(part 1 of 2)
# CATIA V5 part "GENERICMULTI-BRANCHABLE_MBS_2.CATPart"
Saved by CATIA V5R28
Part number: GENERICMULTI-BRANCHABLE_MBS_2
Revision: ---
Publications: "SegmentExtremity.1", "SegmentExtremity.2", "ElecLogTerm.1", "Flexible Curve.1", "Point.4", "SegmentExtremity.3", "SegmentExtremity.4", "ElecLogTerm.2", "Flexible Curve.2", "Point.6", "Point.9", "SegmentExtremity.5", "SegmentExtremity.6", "ElecLogTerm.3", "Flexible Curve.3", "Point.20", "SegmentExtremity.7", "SegmentExtremity.8", "ElecLogTerm.4", "Flexible Curve.4", "CPoint.24", "SegmentExtremity.9", "SegmentExtremity.10", "ElecLogTerm.5", "Flexible Curve.5", "SegmentExtremity.11", "SegmentExtremity.12", "ElecLogTerm.6", "Flexible Curve.6", "SegmentExtremity.13", "SegmentExtremity.14", "ElecLogTerm.7", "Flexible Curve.7", "SegmentExtremity.15", "SegmentExtremity.16", "ElecLogTerm.8", "Flexible Curve.8", "Point.43", "Point.48", "SegmentExtremity.17", "SegmentExtremity.18", "ElecLogTerm.9", "Flexible Curve.9", "SegmentExtremity.19", "SegmentExtremity.20", "ElecLogTerm.10", "Flexible Curve.10", "SegmentExtremity.21", "SegmentExtremity.22", "ElecLogTerm.11", "Flexible Curve.11", "SegmentExtremity.23", "SegmentExtremity.24", "ElecLogTerm.12", "Flexible Curve.12", "SegmentExtremity.25", "SegmentExtremity.26", "ElecLogTerm.13", "Flexible Curve.13", "SegmentExtremity.27", "SegmentExtremity.28", "ElecLogTerm.14", "Flexible Curve.14", "SegmentExtremity.29", "SegmentExtremity.30", "ElecLogTerm.15", "Flexible Curve.15", "SegmentExtremity.31", "SegmentExtremity.32", "ElecLogTerm.16", "Flexible Curve.16", "Point.74", "SegmentExtremity.33", "SegmentExtremity.34", "ElecLogTerm.17", "Flexible Curve.17", "Point.77", "SegmentExtremity.35", "SegmentExtremity.36", "ElecLogTerm.18", "Flexible Curve.18", "SegmentExtremity.37", "SegmentExtremity.38", "ElecLogTerm.19", "Flexible Curve.19", "SegmentExtremity.39", "SegmentExtremity.40", "ElecLogTerm.20", "Flexible Curve.20", "Point.85", "Point.86", "SegmentExtremity.41", "SegmentExtremity.42", "ElecLogTerm.21", "Flexible Curve.21", "SegmentExtremity.43", "SegmentExtremity.44", "ElecLogTerm.22", "Flexible Curve.22", "SegmentExtremity.45", "SegmentExtremity.46", "ElecLogTerm.23", "Flexible Curve.23", "Point.94", "Point.96", "SegmentExtremity.47", "SegmentExtremity.48", "ElecLogTerm.24", "Flexible Curve.24", "SegmentExtremity.49", "SegmentExtremity.50", "ElecLogTerm.25", "Flexible Curve.25", "SegmentExtremity.51", "SegmentExtremity.52", "ElecLogTerm.26", "Flexible Curve.26", "Point.105", "Point.110", "SegmentExtremity.53", "SegmentExtremity.54", "ElecLogTerm.27", "Flexible Curve.27", "Point.117", "SegmentExtremity.55", "SegmentExtremity.56", "ElecLogTerm.28", "Flexible Curve.28", "SegmentExtremity.57", "SegmentExtremity.58", "ElecLogTerm.29", "Flexible Curve.29", "Point.189", "SegmentExtremity.59", "SegmentExtremity.60", "ElecLogTerm.30", "Flexible Curve.30", "Point.229", "SegmentExtremity.61", "SegmentExtremity.62", "ElecLogTerm.31", "Flexible Curve.31", "Point.236", "SegmentExtremity.63", "SegmentExtremity.64", "ElecLogTerm.32", "Flexible Curve.32", "Point.239", "SegmentExtremity.65", "SegmentExtremity.66", "ElecLogTerm.33", "Flexible Curve.33", "SegmentExtremity.67", "SegmentExtremity.68", "ElecLogTerm.34", "Flexible Curve.34", "Point.301", "SegmentExtremity.69", "SegmentExtremity.70", "ElecLogTerm.35", "Flexible Curve.35", "Point.339", "SegmentExtremity.71", "SegmentExtremity.72", "ElecLogTerm.36", "Flexible Curve.36", "Point.371", "SegmentExtremity.73", "SegmentExtremity.74", "ElecLogTerm.37", "Flexible Curve.37", "Point.377", "SegmentExtremity.75", "SegmentExtremity.76", "ElecLogTerm.38", "Flexible Curve.38", "SegmentExtremity.77", "SegmentExtremity.78", "ElecLogTerm.39", "Flexible Curve.39", "Point.394", "SegmentExtremity.79", "SegmentExtremity.80", "ElecLogTerm.40", "Flexible Curve.40", "Point.399", "SegmentExtremity.81", "SegmentExtremity.82", "ElecLogTerm.41", "Flexible Curve.41", "SegmentExtremity.83", "SegmentExtremity.84", "ElecLogTerm.42", "Flexible Curve.42", "SegmentExtremity.85", "SegmentExtremity.86", "ElecLogTerm.43", "Flexible Curve.43", "Point.407", "SegmentExtremity.87", "SegmentExtremity.88", "ElecLogTerm.44", "Flexible Curve.44", "Point.412", "Point.413", "SegmentExtremity.89", "SegmentExtremity.90", "ElecLogTerm.45", "Flexible Curve.45", "SegmentExtremity.91", "SegmentExtremity.92", "ElecLogTerm.46", "Flexible Curve.46", "SegmentExtremity.93", "SegmentExtremity.94", "ElecLogTerm.47", "Flexible Curve.47", "SegmentExtremity.95", "SegmentExtremity.96", "ElecLogTerm.48", "Flexible Curve.48", "Point.428", "SegmentExtremity.97", "SegmentExtremity.98", "ElecLogTerm.49", "Flexible Curve.49", "SegmentExtremity.99", "SegmentExtremity.100", "ElecLogTerm.50", "Flexible Curve.50", "SegmentExtremity.101", "SegmentExtremity.102", "ElecLogTerm.51", "Flexible Curve.51", "SegmentExtremity.103", "SegmentExtremity.104", "ElecLogTerm.52", "Flexible Curve.52", "Point.475", "SegmentExtremity.105", "SegmentExtremity.106", "ElecLogTerm.53", "Flexible Curve.53", "Point.494", "SegmentExtremity.107", "SegmentExtremity.108", "ElecLogTerm.54", "Flexible Curve.54", "BCPRPoint.2", "BCPRPoint.3", "BCPRPoint.4", "BCPRPoint.5", "BCPRPoint.6", "BCPRPoint.7", "BCPRPoint.8", "BCPRPoint.9", "BCPRPoint.10", "BCPRPoint.11", "BCPRPoint.12", "BCPRPoint.13", "BCPRPoint.14", "BCPRPoint.15", "BCPRPoint.16", "BCPRPoint.17", "BCPRPoint.18", "BCPRPoint.19", "BCPRPoint.20", "BCPRPoint.21", "BCPRPoint.22", "Point.525", "Point.526", "Point.527", "Point.528", "Point.529", "Point.530", "Point.531", "Point.532", "Point.533", "Point.534", "Point.537", "Point.538", "Point.539", "Point.540", "Point.541", "Point.542", "Point.543", "Point.544", "Point.545", "Point.546", "Point.547", "Point.548", "Point.549", "Point.550", "Point.551", "Point.552", "Point.554", "Point.555", "Point.556", "Point.557", "Point.558", "Point.559", "Point.560", "Point.561", "Point.562", "Point.563", "Point.564", "Point.565", "Point.566", "Point.567", "Point.568", "Point.569", "Point.570", "Point.571", "Point.572", "Point.573", "Point.574", "Point.179", "BCPRPoint.23", "Point.670", "Point.667", "Point.668", "Point.669", "Point.683", "Project.2", "Point.710", "SegmentExtremity.109", "SegmentExtremity.110", "ElecLogTerm.55", "Flexible Curve.55", "BCPRPoint_generated(BCP).1", "SegmentExtremity.111", "SegmentExtremity.112", "ElecLogTerm.56", "Flexible Curve.56", "BCPRPoint_generated(BCP).2", "BCPRPoint_generated(BCP).3", "SegmentExtremity.113", "SegmentExtremity.114", "ElecLogTerm.57", "Point.729", "SegmentExtremity.115", "SegmentExtremity.116", "ElecLogTerm.58", "Flexible Curve.57", "BCPRPoint_generated(BCP).4", "SegmentExtremity.117", "SegmentExtremity.118", "ElecLogTerm.59", "Flexible Curve.58", "BCPRPoint_generated(BCP).5", "BCPRPoint_generated(BCP).6", "BCPRPoint_generated(BCP).7", "SegmentExtremity.119", "SegmentExtremity.120", "ElecLogTerm.60", "Flexible Curve.59", "BCPRPoint_generated(BCP).8", "Point.408", "Point.409", "Point.467", "Point.466"
Bounding box of the stored display mesh (mm): x 24243.072 to 33945.086, y -22409.492 to -1507.375, z 3643.49 to 6313.591
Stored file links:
  C:\Users\ajc8720\Documents\BOEING_WORK\0001-2CES\004-AP242\Boeing-Generic_Harness_R3\GENERICMULTI-BRANCHABLE_MBS_2.CATPart
  C:\Users\ajc8720\Documents\BOEING_WORK\0001-2CES\004-AP242\Boeing-Generic_Harness_R3\GENERICBUNDLE_GBN_1.CATProduct
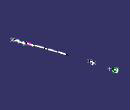
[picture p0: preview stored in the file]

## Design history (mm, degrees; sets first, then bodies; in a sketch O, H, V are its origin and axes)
Sketch1 on {plane type Normal, RefPoint {point type OnCurve, Real 0.5}}, origin (26213.183, -6443.2858, 4604.0933), H (0.9576, 0.2864, -0.0301), V (0, 0.1045, 0.9945)
  circle A1 centre (0, 0) radius 10.795
  point P1 (0, 0)
  reference projected point E1 (0, 0) from {point type OnCurve, Real 0.5}
  radius A1 = 10.795
  distance E1 P1 = 0
ElecRouteBody1
EhiBundleSegmentBody1
Sketch2 on {plane type Normal, RefPoint {point type OnCurve, Real 0.5}}, origin (26256.4001, -6641.2399, 4721.1042), H (0.9062, 0.4205, -0.0442), V (0, 0.1045, 0.9945)
  circle A1 centre (0, 0) radius 9.525
  point P1 (0, 0)
  reference projected point E1 (0, 0) from {point type OnCurve, Real 0.5}
  radius A1 = 9.525
  distance E1 P1 = 0
ElecRouteBody2
EhiBundleSegmentBody2
Sketch3 on {plane type Normal, RefPoint {point type OnCurve, Real 0.5}}, origin (26453.1949, -6991.596, 4803.1154), H (0.93, 0.3504, -0.111), V (0.0006, 0.3004, 0.9538)
  circle A1 centre (-0.9208, 0.0537) radius 9.525
  point P1 (-0.9208, 0.0537)
  reference projected point E1 (-0.9208, 0.0537) from {point type OnCurve, Real 0.5}
  radius A1 = 9.525
  distance E1 P1 = 0
ElecRouteBody3
EhiBundleSegmentBody3
Sketch4 on {plane type Normal, RefPoint {point type OnCurve, Real 0.5}}, origin (26668.956, -7391.5002, 4859.3676), H (0.8885, 0.4564, -0.047), V (0, 0.1023, 0.9947)
  circle A1 centre (0, 0) radius 9.525
  point P1 (0, 0)
  reference projected point E1 (0, 0) from {point type OnCurve, Real 0.5}
  radius A1 = 9.525
  distance E1 P1 = 0
ElecRouteBody4
EhiBundleSegmentBody4
Sketch5 on {plane type Normal, RefPoint {point type OnCurve, Real 0.5}}, origin (27011.036, -6318.2009, 4593.2911), H (0.1287, -0.1353, 0.9824), V (0.0331, 0.9907, 0.1321)
  circle A1 centre (-20.9065, -19.5121) radius 4.0551
  point P1 (-20.9065, -19.5121)
  reference projected point E1 (-20.9065, -19.5121) from {point type OnCurve, Real 0.5}
  radius A1 = 4.0551
  distance E1 P1 = 0
ElecRouteBody5
EhiBundleSegmentBody5
Sketch6 on {plane type Normal, RefPoint {point type OnCurve, Real 0.5}}, origin (49731.4801, -39351.1877, 111363.943), H (-0.0398, 0.9992, 0.0075), V (-0.1997, -0.0006, -0.9799)
  circle A1 centre (32927.0187, 109125.9194) radius 4.0551
  point P1 (32927.0187, 109125.9194)
  reference projected point E1 (32927.0187, 109125.9194) from {point type OnCurve, Real 0.5}
  radius A1 = 4.0551
  distance E1 P1 = 0
ElecRouteBody6
EhiBundleSegmentBody6
Sketch7 on {plane type Normal, RefPoint {point type OnCurve, Real 0.5}}, origin (26989.497, -6324.5713, 4603.6628), H (0.3995, -0.7235, 0.5629), V (-0.0699, 0.5882, 0.8057)
  circle A1 centre (-12.6154, -10.6018) radius 1.905
  point P1 (-12.6154, -10.6018)
  reference projected point E1 (-12.6154, -10.6018) from {point type OnCurve, Real 0.5}
  radius A1 = 1.905
  distance E1 P1 = 0
ElecRouteBody7
EhiBundleSegmentBody7
Sketch8 on {plane type Normal, RefPoint {point type OnCurve, Real 0.5}}, origin (26896.1491, -7390.6456, 4843.5268), H (0.1109, -0.1106, 0.9877), V (0, 0.9938, 0.1112)
  circle A1 centre (0, 0) radius 4.1275
  point P1 (0, 0)
  reference projected point E1 (0, 0) from {point type OnCurve, Real 0.5}
  radius A1 = 4.1275
  distance E1 P1 = 0
ElecRouteBody8
EhiBundleSegmentBody8
Sketch9 on {plane type Normal, RefPoint {point type OnCurve, Real 0.5}}, origin (26695.6549, -7366.8722, 4853.3831), H (0.3387, 0.9392, 0.0562), V (-0.0089, 0.0629, -0.998)
  circle A1 centre (-5.2532, -1.0249) radius 4.1275
  point P1 (-5.2532, -1.0249)
  reference projected point E1 (-5.2532, -1.0249) from {point type OnCurve, Real 0.5}
  radius A1 = 4.1275
  distance E1 P1 = 0
ElecRouteBody9
EhiBundleSegmentBody9
Sketch10 on {plane type Normal, RefPoint {point type OnCurve, Real 0.5}}, origin (26236.2396, -6563.4435, 4663.301), H (0.9909, 0.0973, -0.0929), V (0, -0.6903, -0.7235)
  circle A1 centre (0, 0) radius 6.35
  point P1 (0, 0)
  reference projected point E1 (0, 0) from {point type OnCurve, Real 0.5}
  radius A1 = 6.35
  distance E1 P1 = 0
ElecRouteBody10
EhiBundleSegmentBody10
Sketch11 on {plane type Normal, RefPoint {point type OnCurve, Real 0.5}}, origin (27049.1119, -7384.3587, 4761.522), H (0.9245, -0.0602, -0.3763), V (0, 0.9874, -0.158)
  circle A1 centre (0, 0) radius 2.54
  point P1 (0, 0)
  reference projected point E1 (0, 0) from {point type OnCurve, Real 0.5}
  radius A1 = 2.54
  distance E1 P1 = 0
ElecRouteBody11
EhiBundleSegmentBody11
Sketch12 on {plane type Normal, RefPoint {point type OnCurve, Real 0.5}}, origin (26128.5708, -5138.6732, 4494.0283), H (0.4828, 0.1657, -0.8599), V (0.1158, -0.9854, -0.1249)
  circle A1 centre (-1.9758, -6.4321) radius 1.905
  point P1 (-1.9758, -6.4321)
  reference projected point E1 (-1.9758, -6.4321) from {point type OnCurve, Real 0.5}
  radius A1 = 1.905
  distance E1 P1 = 0
ElecRouteBody12
EhiBundleSegmentBody12
Sketch13 on {plane type Normal, RefPoint {point type OnCurve, Real 0.5}}, origin (26107.9693, -5243.6064, 4514.0548), H (0.4828, 0.1659, -0.8599), V (0.1159, -0.9854, -0.125)
  circle A1 centre (-1.9849, -6.4169) radius 1.905
  point P1 (-1.9849, -6.4169)
  reference projected point E1 (-1.9849, -6.4169) from {point type OnCurve, Real 0.5}
  radius A1 = 1.905
  distance E1 P1 = 0
ElecRouteBody13
EhiBundleSegmentBody13
Sketch14 on {plane type Normal, RefPoint {point type OnCurve, Real 0.5}}, origin (26097.0495, -5135.4084, 4453.8298), H (0.9908, -0.1276, -0.0444), V (-0.0273, 0.1326, -0.9908)
  circle A1 centre (-20.4324, 12.3549) radius 3.81
  point P1 (-20.4324, 12.3549)
  reference projected point E1 (-20.4324, 12.3549) from {point type OnCurve, Real 0.5}
  radius A1 = 3.81
  distance E1 P1 = 0
ElecRouteBody14
EhiBundleSegmentBody14
Sketch15 on {plane type Normal, RefPoint {point type OnCurve, Real 0.5}}, origin (26102.9361, -5259.1919, 4430.3629), H (0.9027, 0.2796, 0.3272), V (-0.0137, 0.7785, -0.6274)
  circle A1 centre (-3.249, 5.8767) radius 3.81
  point P1 (-3.249, 5.8767)
  reference projected point E1 (-3.249, 5.8767) from {point type OnCurve, Real 0.5}
  radius A1 = 3.81
  distance E1 P1 = 0
ElecRouteBody15
EhiBundleSegmentBody15
Sketch16 on {plane type Normal, RefPoint {point type OnCurve, Real 0.5}}, origin (26042.6946, -5529.0738, 4602.6872), H (0.4364, -0.7464, 0.5025), V (0.0348, 0.572, 0.8195)
  circle A1 centre (9.9402, -2.3183) radius 2.54
  point P1 (9.9402, -2.3183)
  reference projected point E1 (9.9402, -2.3183) from {point type OnCurve, Real 0.5}
  radius A1 = 2.54
  distance E1 P1 = 0
ElecRouteBody16
EhiBundleSegmentBody16
Sketch17 on {plane type Normal, RefPoint {point type OnCurve, Real 0.5}}, origin (25968.1593, -5541.3146, 4616.3826), H (0.0351, -0.0718, -0.9968), V (0, -0.9974, 0.0719)
  circle A1 centre (0, 0) radius 2.54
  point P1 (0, 0)
  reference projected point E1 (0, 0) from {point type OnCurve, Real 0.5}
  radius A1 = 2.54
  distance E1 P1 = 0
ElecRouteBody17
EhiBundleSegmentBody17
Sketch18 on {plane type Normal, RefPoint {point type OnCurve, Real 0.5}}, origin (25928.9352, -5542.4868, 4617.775), H (0.1622, -0.1298, 0.9782), V (-0.0107, 0.991, 0.1333)
  circle A1 centre (-1.6298, -0.282) radius 1.905
  point P1 (-1.6298, -0.282)
  reference projected point E1 (-1.6298, -0.282) from {point type OnCurve, Real 0.5}
  radius A1 = 1.905
  distance E1 P1 = 0
ElecRouteBody18
EhiBundleSegmentBody18
Sketch19 on {plane type Normal, RefPoint {point type OnCurve, Real 0.5}}, origin (25969.5148, -5543.6441, 4618.1771), H (0.51, -0.5087, 0.6936), V (0, -0.8064, -0.5914)
  circle A1 centre (0, 0) radius 1.905
  point P1 (0, 0)
  reference projected point E1 (0, 0) from {point type OnCurve, Real 0.5}
  radius A1 = 1.905
  distance E1 P1 = 0
ElecRouteBody19
EhiBundleSegmentBody19
Sketch20 on {plane type Normal, RefPoint {point type OnCurve, Real 0.5}}, origin (30670.7863, -16023.3411, 5695.8425), H (0.0495, 0.3386, -0.9396), V (0.0176, 0.9403, 0.3398)
  circle A1 centre (-1.9655, -2.0978) radius 4.4577
  point P1 (-1.9655, -2.0978)
  reference projected point E1 (-1.9655, -2.0978) from {point type OnCurve, Real 0.5}
  radius A1 = 4.4577
  distance E1 P1 = 0
ElecRouteBody20
EhiBundleSegmentBody20
Sketch21 on {plane type Normal, RefPoint {point type OnCurve, Real 0.5}}, origin (30705.4895, -15985.8971, 5696.0522), H (0.9904, 0.1378, -0.0101), V (0, -0.0734, -0.9973)
  circle A1 centre (0, 0) radius 4.4577
  point P1 (0, 0)
  reference projected point E1 (0, 0) from {point type OnCurve, Real 0.5}
  radius A1 = 4.4577
  distance E1 P1 = 0
ElecRouteBody21
EhiBundleSegmentBody21
Sketch22 on {plane type Normal, RefPoint {point type OnCurve, Real 0.5}}, origin (30698.767, -15966.8699, 5655.2829), H (0.999, -0.045, 0.0086), V (0, 0.1871, 0.9823)
  circle A1 centre (0, 0) radius 1.905
  point P1 (0, 0)
  reference projected point E1 (0, 0) from {point type OnCurve, Real 0.5}
  radius A1 = 1.905
  distance E1 P1 = 0
ElecRouteBody22
EhiBundleSegmentBody22
Sketch23 on {plane type Normal, RefPoint {point type OnCurve, Real 0.5}}, origin (28685.6847, -11813.3322, 5280.2662), H (0.8036, -0.0518, 0.5929), V (-0.0111, 0.9947, 0.102)
  circle A1 centre (-0.5557, -3.6236) radius 3.81
  point P1 (-0.5557, -3.6236)
  reference projected point E1 (-0.5557, -3.6236) from {point type OnCurve, Real 0.5}
  radius A1 = 3.81
  distance E1 P1 = 0
ElecRouteBody23
EhiBundleSegmentBody23
Sketch24 on {plane type Normal, RefPoint {point type OnCurve, Real 0.5}}, origin (28677.0755, -11774.8153, 5303.0023), H (0.798, -0.5947, 0.0978), V (0, -0.1622, -0.9868)
  circle A1 centre (0.0001, 0) radius 3.81
  point P1 (0.0001, 0)
  reference projected point E1 (0.0001, 0) from {point type OnCurve, Real 0.5}
  radius A1 = 3.81
  distance E1 P1 = 0
ElecRouteBody24
EhiBundleSegmentBody24
Sketch25 on {plane type Normal, RefPoint {point type OnCurve, Real 0.5}}, origin (28722.2891, -11781.9897, 5268.5204), H (0.8943, -0.4309, 0.1207), V (-0.0577, -0.3785, -0.9238)
  circle A1 centre (3.5246, 5.3989) radius 1.905
  point P1 (3.5246, 5.3989)
  reference projected point E1 (3.5246, 5.3989) from {point type OnCurve, Real 0.5}
  radius A1 = 1.905
  distance E1 P1 = 0
ElecRouteBody25
EhiBundleSegmentBody25
Sketch26 on {plane type Normal, RefPoint {point type OnCurve, Real 0.5}}, origin (33563.3292, -22218.4684, 6290.6188), H (0.8596, 0.4988, -0.1108), V (0.0778, -0.3421, -0.9364)
  circle A1 centre (0.5333, -0.4631) radius 6.35
  point P1 (0.5333, -0.4631)
  reference projected point E1 (0.5333, -0.4631) from {point type OnCurve, Real 0.5}
  radius A1 = 6.35
  distance E1 P1 = 0
ElecRouteBody26
EhiBundleSegmentBody26
Sketch27 on {plane type Normal, RefPoint {point type OnCurve, Real 0.5}}, origin (33490.3918, -22021.0196, 6222.6941), H (0.906, 0.4227, -0.0228), V (0.0157, -0.0874, -0.996)
  circle A1 centre (-1.4661, -0.703) radius 6.35
  point P1 (-1.4661, -0.703)
  reference projected point E1 (-1.4661, -0.703) from {point type OnCurve, Real 0.5}
  radius A1 = 6.35
  distance E1 P1 = 0
ElecRouteBody27
EhiBundleSegmentBody27
Sketch28 on {plane type Normal, RefPoint {point type OnCurve, Real 0.5}}, origin (33352.8696, -20886.2952, 6113.4253), H (0.943, 0.257, -0.2116), V (-0.1712, -0.1709, -0.9703)
  circle A1 centre (-75.6653, -27.5513) radius 6.35
  point P1 (-75.6653, -27.5513)
  reference projected point E1 (-75.6653, -27.5513) from {point type OnCurve, Real 0.5}
  radius A1 = 6.35
  distance E1 P1 = 0
ElecRouteBody28
EhiBundleSegmentBody28
Sketch29 on {plane type Normal, RefPoint {point type OnCurve, Real 0.5}}, origin (32432.7949, -19746.6017, 6003.1968), H (0.6035, 0.793, -0.0834), V (0, -0.1045, -0.9945)
  circle A1 centre (-0.0009, -0.0017) radius 8.7503
  point P1 (-0.0009, -0.0017)
  reference projected point E1 (-0.0009, -0.0017) from {point type OnCurve, Real 0.5}
  radius A1 = 8.7503
  distance E1 P1 = 0
ElecRouteBody29
EhiBundleSegmentBody29
Sketch30 on {plane type Normal, RefPoint {point type OnCurve, Real 0.5}}, origin (31928.5727, -18771.5149, 5899.2872), H (0.7094, 0.6964, 0.1084), V (-0.0037, 0.1574, -0.9875)
  circle A1 centre (0.2663, 9.5618) radius 8.7503
  point P1 (0.2663, 9.5618)
  reference projected point E1 (0.2663, 9.5618) from {point type OnCurve, Real 0.5}
  radius A1 = 8.7503
  distance E1 P1 = 0
ElecRouteBody30
EhiBundleSegmentBody30
Sketch31 on {plane type Normal, RefPoint {point type OnCurve, Real 0.5}}, origin (31658.6057, -18229.442, 5720.6349), H (0.9067, 0.4089, -0.1034), V (-0.034, -0.1735, -0.9843)
  circle A1 centre (14.6504, 0.9293) radius 8.7503
  point P1 (14.6504, 0.9293)
  reference projected point E1 (14.6504, 0.9293) from {point type OnCurve, Real 0.5}
  radius A1 = 8.7503
  distance E1 P1 = 0
ElecRouteBody31
EhiBundleSegmentBody31
Sketch32 on {plane type Normal, RefPoint {point type OnCurve, Real 0.5}}, origin (31549.3665, -18111.0883, 5685.3238), H (0.8772, 0.4623, 0.13), V (0.1495, -0.0056, -0.9888)
  circle A1 centre (92.5637, -9.1563) radius 8.7503
  point P1 (92.5637, -9.1563)
  reference projected point E1 (92.5637, -9.1563) from {point type OnCurve, Real 0.5}
  radius A1 = 8.7503
  distance E1 P1 = 0
ElecRouteBody32
EhiBundleSegmentBody32
Sketch33 on {plane type Normal, RefPoint {point type OnCurve, Real 0.5}}, origin (31140.6727, -17058.6051, 5781.4119), H (0.9103, 0.4026, 0.0965), V (0.171, -0.1531, -0.9733)
  circle A1 centre (-3.7175, -5.8173) radius 9.906
  point P1 (-3.7175, -5.8173)
  reference projected point E1 (-3.7175, -5.8173) from {point type OnCurve, Real 0.5}
  radius A1 = 9.906
  distance E1 P1 = 0
ElecRouteBody33
EhiBundleSegmentBody33
Sketch34 on {plane type Normal, RefPoint {point type OnCurve, Real 0.5}}, origin (30494.6687, -15726.8517, 5629.4109), H (0.8888, 0.4495, -0.089), V (-0.0866, -0.0261, -0.9959)
  circle A1 centre (0.3338, 2.1624) radius 10.795
  point P1 (0.3338, 2.1624)
  reference projected point E1 (0.3338, 2.1624) from {point type OnCurve, Real 0.5}
  radius A1 = 10.795
  distance E1 P1 = 0
ElecRouteBody34
EhiBundleSegmentBody34
Sketch35 on {plane type Normal, RefPoint {point type OnCurve, Real 0.5}}, origin (29943.2257, -14487.599, 5558.011), H (0.862, 0.5054, -0.0403), V (0.0015, -0.0821, -0.9966)
  circle A1 centre (0.2961, -0.199) radius 11.43
  point P1 (0.2961, -0.199)
  reference projected point E1 (0.2961, -0.199) from {point type OnCurve, Real 0.5}
  radius A1 = 11.43
  distance E1 P1 = 0
ElecRouteBody35
EhiBundleSegmentBody35
Sketch36 on {plane type Normal, RefPoint {point type OnCurve, Real 0.5}}, origin (29158.2279, -12800.4042, 5388.3051), H (0.926, 0.3732, -0.056), V (0, -0.1484, -0.9889)
  circle A1 centre (0, 0) radius 12.065
  point P1 (0, 0)
  reference projected point E1 (0, 0) from {point type OnCurve, Real 0.5}
  radius A1 = 12.065
  distance E1 P1 = 0
ElecRouteBody36
EhiBundleSegmentBody36
Sketch37 on {plane type Normal, RefPoint {point type OnCurve, Real 0.5}}, origin (28789.2911, -12029.6656, 5299.0948), H (0.9056, 0.4233, -0.0251), V (0, -0.0591, -0.9983)
  circle A1 centre (0, 0) radius 12.065
  point P1 (0, 0)
  reference projected point E1 (0, 0) from {point type OnCurve, Real 0.5}
  radius A1 = 12.065
  distance E1 P1 = 0
ElecRouteBody37
EhiBundleSegmentBody37
Sketch38 on {plane type Normal, RefPoint {point type OnCurve, Real 0.5}}, origin (28725.2959, -11869.8181, 5292.1257), H (0.9238, 0.361, -0.1278), V (0, -0.3339, -0.9426)
  circle A1 centre (0, 0) radius 13.335
  point P1 (0, 0)
  reference projected point E1 (0, 0) from {point type OnCurve, Real 0.5}
  radius A1 = 13.335
  distance E1 P1 = 0
ElecRouteBody38
EhiBundleSegmentBody38
Sketch39 on {plane type Normal, RefPoint {point type OnCurve, Real 0.5}}, origin (28625.0596, -11647.9066, 5232.3129), H (0.8827, 0.4662, -0.0593), V (-0.0002, -0.1258, -0.9921)
  circle A1 centre (-0.0036, -0.0089) radius 13.97
  point P1 (-0.0036, -0.0089)
  reference projected point E1 (-0.0036, -0.0089) from {point type OnCurve, Real 0.5}
  radius A1 = 13.97
  distance E1 P1 = 0
ElecRouteBody39
EhiBundleSegmentBody39
Sketch40 on {plane type Normal, RefPoint {point type OnCurve, Real 0.5}}, origin (33694.3185, -22246.9568, 6292.6891), H (0.7474, -0.6569, 0.0995), V (-0.0508, -0.2058, -0.9773)
  circle A1 centre (2.0271, -2.0286) radius 3.175
  point P1 (2.0271, -2.0286)
  reference projected point E1 (2.0271, -2.0286) from {point type OnCurve, Real 0.5}
  radius A1 = 3.175
  distance E1 P1 = 0
ElecRouteBody40
EhiBundleSegmentBody40
Sketch41 on {plane type Normal, RefPoint {point type OnCurve, Real 0.5}}, origin (49861.2517, -40374.0355, -34674.9732), H (-0.2509, -0.8819, 0.3991), V (0.3155, -0.4642, -0.8276)
  circle A1 centre (4419.6352, -47275.572) radius 3.175
  point P1 (4419.6352, -47275.572)
  reference projected point E1 (4419.6352, -47275.572) from {point type OnCurve, Real 0.5}
  radius A1 = 3.175
  distance E1 P1 = 0
ElecRouteBody41
EhiBundleSegmentBody41
Sketch42 on {plane type Normal, RefPoint {point type OnCurve, Real 0.5}}, origin (33820.5319, -22268.5841, 6260.7248), H (0.8207, 0.3801, 0.4266), V (0.0319, -0.776, 0.6299)
  circle A1 centre (-1.5951, -2.5595) radius 1.905
  point P1 (-1.5951, -2.5595)
  reference projected point E1 (-1.5951, -2.5595) from {point type OnCurve, Real 0.5}
  radius A1 = 1.905
  distance E1 P1 = 0
ElecRouteBody42
EhiBundleSegmentBody42
Sketch43 on {plane type Normal, RefPoint {point type OnCurve, Real 0.5}}, origin (25423.0221, -1627.0277, 4861.8956), H (0.9938, 0.1003, -0.0486), V (-0.0899, 0.4643, -0.8811)
  circle A1 centre (5.3852, 34.4799) radius 4.2545
  point P1 (5.3852, 34.4799)
  reference projected point E1 (5.3852, 34.4799) from {point type OnCurve, Real 0.5}
  radius A1 = 4.2545
  distance E1 P1 = 0
ElecRouteBody43
EhiBundleSegmentBody43
Sketch44 on {plane type Normal, RefPoint {point type OnCurve, Real 0.5}}, origin (25487.4489, -1771.0394, 4822.5851), H (0.7597, -0.6192, 0.1985), V (0.0047, -0.2999, -0.9539)
  circle A1 centre (-7.2115, -0.0119) radius 6.0579
  point P1 (-7.2115, -0.0119)
  reference projected point E1 (-7.2115, -0.0119) from {point type OnCurve, Real 0.5}
  radius A1 = 6.0579
  distance E1 P1 = 0
ElecRouteBody44
EhiBundleSegmentBody44
Sketch45 on {plane type Normal, RefPoint {point type OnCurve, Real 0.5}}, origin (25531.3423, -1632.8756, 4798.3449), H (0.9922, 0.1235, -0.0175), V (-0.0044, -0.1058, -0.9944)
  circle A1 centre (-1.3388, -1.2379) radius 4.5466
  point P1 (-1.3388, -1.2379)
  reference projected point E1 (-1.3388, -1.2379) from {point type OnCurve, Real 0.5}
  radius A1 = 4.5466
  distance E1 P1 = 0
ElecRouteBody45
EhiBundleSegmentBody45
Sketch46 on {plane type Normal, RefPoint {point type OnCurve, Real 0.5}}, origin (25453.2751, -1763.5738, 4820.3746), H (0.9999, 0.0115, -0.0035), V (0, -0.2854, -0.9584)
  circle A1 centre (-1.2692, -0.0042) radius 8.509
  point P1 (-1.2692, -0.0042)
  reference projected point E1 (-1.2692, -0.0042) from {point type OnCurve, Real 0.5}
  radius A1 = 8.509
  distance E1 P1 = 0
ElecRouteBody46
EhiBundleSegmentBody46
Sketch47 on {plane type Normal, RefPoint {point type OnCurve, Real 0.5}}, origin (25436.4996, -1635.6897, 4799.4859), H (0.9981, -0.062, 0.0066), V (0.0023, -0.0695, -0.9976)
  circle A1 centre (0.4671, -0.5485) radius 4.7625
  point P1 (0.4671, -0.5485)
  reference projected point E1 (0.4671, -0.5485) from {point type OnCurve, Real 0.5}
  radius A1 = 4.7625
  distance E1 P1 = 0
ElecRouteBody47
EhiBundleSegmentBody47
Sketch48 on {plane type Normal, Curve {split Cutting Point25}, RefPoint {point type OnCurve, Support {split Cutting Point25}, Real 0.5}}, origin (24269.9929, -1920.7223, 4181.7535), H (0.9988, -0.0208, 0.0439), V (-0.0208, -0.9998, -0.0009)
  circle A1 centre (-18.3771, -10.2752) radius 2.54
  point P1 (-18.3771, -10.2752)
  reference projected point E1 (-18.3771, -10.2752) from {point type OnCurve, Support {split Cutting Point25}, Real 0.5}
  radius A1 = 2.54
  distance E1 P1 = 0
Sketch49 on {plane type Normal, RefPoint {point type OnCurve, Support {split Cutting Point25}, split-ratio-1 0.5}}, origin (24466.2896, -2229.9501, 3688.3738), H (0.934, -0.1049, 0.3415), V (0, 0.9559, 0.2937)
  circle A1 centre (0, 0) radius 2.54
  point P1 (0, 0)
  reference projected point E1 (0, 0) from {point type OnCurve, Support {split Cutting Point25}, split-ratio-1 0.5}
  radius A1 = 2.54
  distance E1 P1 = 0
ElecRouteBody48
EhiBundleSegmentBody48
Sketch50 on {plane type Normal, RefPoint {point type OnCurve, Real 0.5}}, origin (25530.2965, -1633.7389, 4802.2479), H (0.9843, 0.1622, 0.0701), V (-0.0033, 0.4134, -0.9105)
  circle A1 centre (-0.1329, 0.6599) radius 2.032
  point P1 (-0.1329, 0.6599)
  reference projected point E1 (-0.1329, 0.6599) from {point type OnCurve, Real 0.5}
  radius A1 = 2.032
  distance E1 P1 = 0
ElecRouteBody49
EhiBundleSegmentBody49
Sketch51 on {plane type Normal, RefPoint {point type OnCurve, Real 0.5}}, origin (25445.4728, -1631.803, 4798.2463), H (0.8856, -0.4605, 0.0606), V (0.041, -0.0525, -0.9978)
  circle A1 centre (10.8307, 6.1755) radius 4.3434
  point P1 (10.8307, 6.1755)
  reference projected point E1 (10.8307, 6.1755) from {point type OnCurve, Real 0.5}
  radius A1 = 4.3434
  distance E1 P1 = 0
ElecRouteBody50
EhiBundleSegmentBody50
Sketch52 on {plane type Normal, RefPoint {point type OnCurve, Real 0.5}}, origin (25537.2479, -1621.9161, 4799.6132), H (0.8323, -0.5542, 0.0136), V (-0.1299, -0.2188, -0.9671)
  circle A1 centre (-0.0076, 2.5313) radius 4.0132
  point P1 (-0.0076, 2.5313)
  reference projected point E1 (-0.0076, 2.5313) from {point type OnCurve, Real 0.5}
  radius A1 = 4.0132
  distance E1 P1 = 0
ElecRouteBody51
EhiBundleSegmentBody51
Sketch53 on {plane type Normal, RefPoint {point type OnCurve, Real 0.5}}, origin (25052.7144, -1797.5047, 4715.3192), H (0.5321, -0.1079, -0.8398), V (0.0073, -0.9912, 0.132)
  circle A1 centre (-0.0033, -0.0007) radius 10.8966
  point P1 (-0.0033, -0.0007)
  reference projected point E1 (-0.0033, -0.0007) from {point type OnCurve, Real 0.5}
  radius A1 = 10.8966
  distance E1 P1 = 0
ElecRouteBody52
EhiBundleSegmentBody52
Sketch54 on {plane type Normal, RefPoint {point type OnCurve, Real 0.5}}, origin (24690.0569, -2137.3305, 4412.0745), H (0.9496, 0.2774, 0.1458), V (0, -0.465, 0.8853)
  circle A1 centre (0, 0) radius 10.6934
  point P1 (0, 0)
  reference projected point E1 (0, 0) from {point type OnCurve, Real 0.5}
  radius A1 = 10.6934
  distance E1 P1 = 0
ElecRouteBody53
EhiBundleSegmentBody53
Sketch55 on {plane type Normal, RefPoint {point type OnCurve, Real 0.5}}, origin (25375.5414, -1821.7884, 4831.6819), H (0.2882, -0.9504, 0.1171), V (-0.0267, -0.1302, -0.9911)
  circle A1 centre (-1.2073, -1.4272) radius 10.8966
  point P1 (-1.2073, -1.4272)
  reference projected point E1 (-1.2073, -1.4272) from {point type OnCurve, Real 0.5}
  radius A1 = 10.8966
  distance E1 P1 = 0
ElecRouteBody54
EhiBundleSegmentBody54
Sketch56 on {plane type Normal, RefPoint {point type OnCurve, Real 0.5}}, origin (33808.7666, -22338.0001, 6206.226), H (0.8717, 0.4612, 0.1657), V (-0.3049, 0.2458, 0.9201)
  circle A1 centre (-18.6511, -0.7939) radius 3.5052
  point P1 (-18.6511, -0.7939)
  reference projected point E1 (-18.6511, -0.7939) from {point type OnCurve, Real 0.5}
  radius A1 = 3.5052
  distance E1 P1 = 0
ElecRouteBody55
EhiBundleSegmentBody55
Sketch57 on {plane type Normal, RefPoint {point type OnCurve, Real 0.5}}, origin (33856.5953, -22351.2487, 6240.6769), H (-0.0939, 0.9947, 0.0425), V (-0.2897, -0.0681, 0.9547)
  circle A1 centre (34.455, -23.561) radius 3.5052
  point P1 (34.455, -23.561)
  reference projected point E1 (34.455, -23.561) from {point type OnCurve, Real 0.5}
  radius A1 = 3.5052
  distance E1 P1 = 0
ElecRouteBody56
EhiBundleSegmentBody56
EhiBundleSegmentBody57
Sketch58 on {plane type Normal, RefPoint {point type OnCurve, Real 0.5}}, origin (24426.5807, -2286.0422, 3675.1587), H (0.4914, -0.6382, 0.5926), V (0.2678, 0.7582, 0.5945)
  circle A1 centre (-19.1683, 50.4292) radius 2.54
  point P1 (-19.1683, 50.4292)
  reference projected point E1 (-19.1683, 50.4292) from {point type OnCurve, Real 0.5}
  radius A1 = 2.54
  distance E1 P1 = 0
ElecRouteBody57
EhiBundleSegmentBody58
Sketch59 on {plane type Normal, RefPoint {point type OnCurve, Real 0.5}}, origin (24475.2482, -2278.4631, 3680.0542), H (0.8174, 0.4302, -0.3831), V (-0.3576, 0.9004, 0.2479)
  circle A1 centre (37.9261, 36.191) radius 2.54
  point P1 (37.9261, 36.191)
  reference projected point E1 (37.9261, 36.191) from {point type OnCurve, Real 0.5}
  radius A1 = 2.54
  distance E1 P1 = 0
ElecRouteBody58
EhiBundleSegmentBody59
Sketch60 on {plane type Normal, RefPoint {point type OnCurve, Real 0.5}}, origin (25428.2479, -1635.9938, 4886.105), H (0.9894, 0.1427, 0.0272), V (-0.069, 0.6264, -0.7764)
  circle A1 centre (-2.2484, 38.7097) radius 3.175
  point P1 (-2.2484, 38.7097)
  reference projected point E1 (-2.2484, 38.7097) from {point type OnCurve, Real 0.5}
  radius A1 = 3.175
  distance E1 P1 = 0
ElecRouteBody59
EhiBundleSegmentBody60
Set1 "ASSEMBLY_NOTES"
  Point1 "GREEN569-1": type OnCurve, RefPoint Point374, Length 6.35
  Point2 "GREEN569-29": type OnCurve, RefPoint Point328, Length 6.35
  Point3 "GREEN569-125": type OnCurve, RefPoint Point358, Length 6.35
  Point4 "GREEN569-125(1)": type OnCurve, RefPoint Point358, Length 6.35
  Point5 "GREEN569-125(2)": type OnCurve, RefPoint Point358, Length 6.35
  Point6 "GREEN569-127": type OnCurve, RefPoint Point360, Length 6.35
  Point7 "GREEN569-127(1)": type OnCurve, RefPoint Point360, Length 6.35
  Point8 "GREEN569-127(2)": type OnCurve, RefPoint Point360, Length 6.35
  Point9 "PURPLE375-7": type OnCurve, RefPoint Point143, Length 6.35
  Point10 "S4-D1574": type OnCurve, Length 50.8
  Point11 "S8-D2292": type OnCurve, Length 290.9253
  Point12 "SF-1(1)": type OnCurve, RefPoint Point123, Length 38.1
  Point13 "SF-1(2)": type OnCurve, RefPoint Point104, Length 38.1
  Point14 "SR-D1638": type OnCurve, RefPoint Point472, Length 101.6
  Point15 "VAPORSEAL": type OnCurve, RefPoint Point71, Length 20.32
  Point16 "VAPORSEAL(1)": type OnCurve, RefPoint Point44, Length 21.59
  Point17 "START_H00560": type OnCurve, Length 254
  Point18 "END_H00560": type OnCurve, Length 635
  Point19 "SL-H14345": type OnCurve, Length 152.4
  Point20 "AKY": type OnCurve, Length 2819.4
  Point21 "SSTRTIE": type OnCurve, Length 127
  Point22 "CG3": type OnCurve, Length 50.8
  Point23 "TAPE BUILDUP DIAMETER=0.50": type OnCurve, Length 50.8
  Point24 "SM3": type OnCurve, Support DatumCurve1, Length 127
  Point25: type OnCurve, RefPoint Point469, Ratio 0.0760876
  Point26: type OnCurve, Support {line type PtPt, FirstPoint {project ToProject Point473, Support Plane12}, SecondPoint Point473}, RefPoint {project ToProject Point473, Support Plane12}, Length 4.2545
  Project1: ToProject Point26, Support Plane11
  Point27: type OnCurve, Support {line type PtPt, FirstPoint {project ToProject Point475, Support Plane14}, SecondPoint Point475}, RefPoint {project ToProject Point475, Support Plane14}, Length 3.175
  Project2: ToProject Point27, Support Plane11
